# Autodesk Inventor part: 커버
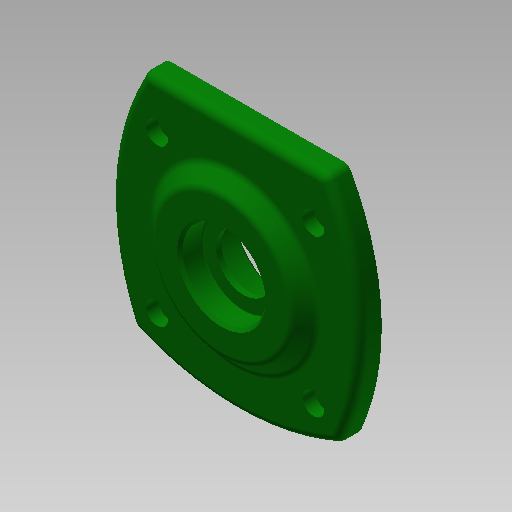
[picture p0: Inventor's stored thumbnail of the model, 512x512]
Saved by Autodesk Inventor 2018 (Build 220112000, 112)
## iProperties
Created: 2016-05
Part Number: 커버
Document SubType Name: Modeling
Designer: mduedu
Density: 2.71 g/cm^3
Material: 알루미늄 6061
Appearance: 진녹색
Author: mduedu
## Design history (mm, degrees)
sketch "스케치1"
  geometry: L1 (0, 0)-(-37.029, 37.029); L2 (0, 0)-(0, 45); L3 (0, 0)-(45, 0); L4 (32.942, 45)-(-32.942, 45); C1 r 25 at (0, 0); A1 r 90 centre (45, 0) between (-32.942, 45) and (-37.029, -37.029); A2 r 90 centre (0, 45) between (-37.029, -37.029) and (37.029, -37.029); A3 r 90 centre (-45, 0) between (37.029, -37.029) and (32.942, 45); 2 further points
  constraints: 9 point on circle, 8 end point, 4 centre point, 2 horizontal alignment, 2 vertical alignment, 1 coincident, 1 equal radius, 1 horizontal, 1 midpoint, 1 parallel, 1 other
  dimensions: "d28" = 90 distance between centres of A3 A1; "d30" = 50 diameter of C1; "d31" = 45 deg angle of L2 L1; "d33" = 90 distance from line of L4 point (0, -45); "d35" = 45 distance from line of L4 A1.centre (= 0.5 x d33); "d36" = 45 distance from line of L2 A1.centre (= 0.5 x d28)
extrude "돌출1" new body sketch "스케치1" distance "d0" = 8; taper "d1" = 0 deg
extrude "돌출2" join sketch "스케치1" distance "d2" = 12; taper "d3" = 0 deg
sketch "스케치2"
  geometry: C1 r 30 at (0, 0); 1 further point
  constraints: 1 centre point, 1 coincident
  dimensions: "d4" = 60 diameter of C1
extrude "돌출3" join sketch "스케치2" distance "d5" = 5; taper "d6" = -45 deg
sketch "스케치3"
  geometry: C1 r 1.621 at (-28.284, 28.284) reference; C2 r 1.621 at (28.284, 28.284) reference; C3 r 1.621 at (28.284, -28.284) reference; C4 r 1.621 at (-28.284, -28.284) reference; 1 further point
hole "구멍1" sketch "스케치3" at (28.284, 28.284), (-28.284, 28.284), (-28.284, -28.284), (28.284, -28.284) diameter "d7" = 4.5; stored, may be unused: countersink angle "d11" = 90 deg, drill point angle "d13" = 118 deg; dims "d8" = 6, "d9" = 8, "d10" = 4.4, "d12" = 8
fillet "모깎기1" dims "d14" = 3
sketch "스케치4"
  geometry: L1 (-23.757, 13)-(23.757, 13) reference; L2 (25, -12)-(-25, -12) reference; L3 (0, -12)-(0, 13); L4 (-20, -12)-(-20, 0); L5 (-20, 0)-(-15, 0); L6 (-15, 0)-(-15, 3); L7 (-15, 3)-(-10, 3); L8 (-10, 3)-(-10, 5); L9 (-10, 5)-(-15, 5); L10 (-15, 5)-(-15, 13); 1 further point
  constraints: 16 end point, 6 parallel, 2 midpoint, 2 point on line, 1 perpendicular
  dimensions: "d15" = 40 diameter of L4 L3; "d16" = 30 diameter of L10 L3; "d17" = 8 distance of L9.end L10.end; "d18" = 12 distance of L4.start L4.end; "d19" = 3 distance of L5.end L6.end; "d20" = 30 diameter of L6 L3; "d21" = 20 diameter of L8 L3
revolve "회전1" sketch "스케치4" stored, may be unused: angle "d22" = 90 deg
fillet "모깎기2" dims "d23" = 3
fillet "모깎기3" dims "d24" = 0.3
chamfer "모따기1" distance "d25" = 1; stored, may be unused: second distance "d26" = 2, angle "d27" = 45 deg
node "솔리드1"
node "참조2"
node "참조3"
node "참조4"
node "참조5"
